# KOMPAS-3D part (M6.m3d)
File: created 17.03.2016 12:24:08, last saved 18.09.2016 12:04:08.
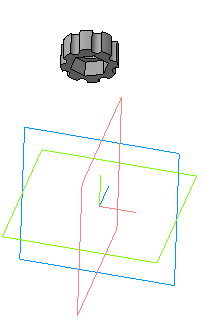
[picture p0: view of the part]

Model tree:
1. Эскиз:1
2. Операция выдавливания:1
     Расстояние 1 = 12
3. Эскиз:2
4. Вырезать элемент выдавливания:1
     Расстояние 1 = 20
5. Эскиз:3
6. Вырезать элемент выдавливания:2
     Расстояние 1 = 10
7. Скругление:1
     Радиус = 7
8. Скругление:2
     Радиус = 7
9. Скругление:3
     Радиус = 13
10. Эскиз:4
11. Вырезать элемент выдавливания:3
     Расстояние 1 = 20
12. Эскиз:5
13. Операция выдавливания:2
     Расстояние 1 = 1.5
14. Эскиз:6
15. Операция выдавливания:3
     Расстояние 1 = 1.5; Расстояние 2 = 12
16. Эскиз:7
17. Вырезать элемент выдавливания:4
     Расстояние 1 = 20
18. Эскиз:8
19. Вырезать элемент выдавливания:5
     Расстояние 2 = 30; Расстояние 1 = 30
20. Масштабирование:2
     Коэффициент = 1.06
